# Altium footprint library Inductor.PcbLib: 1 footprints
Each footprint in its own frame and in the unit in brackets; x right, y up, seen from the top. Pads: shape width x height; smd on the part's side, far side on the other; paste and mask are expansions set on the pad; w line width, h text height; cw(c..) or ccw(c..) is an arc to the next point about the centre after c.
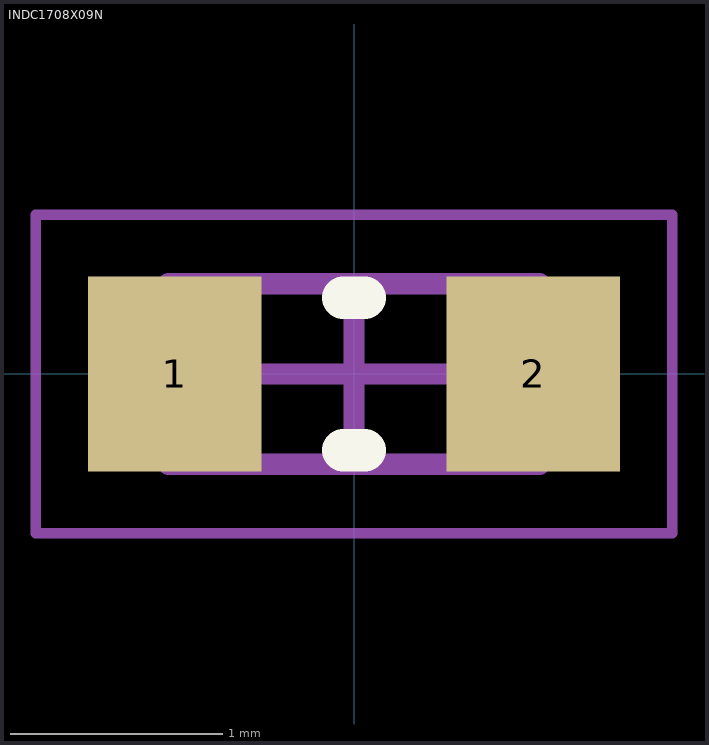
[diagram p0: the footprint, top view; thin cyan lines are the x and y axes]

## INDC1708X09N [mm] "Chip Inductor, 2-Leads, Body 1.70x0.80mm, IPC Medium Density"
height 0.9
pads (2):
  rect 0.82x0.92 smd: 1(-0.845,0) 2(0.845,0)
Top Overlay:
  lines w0.2: -0.05,-0.36 0.05,-0.36 ; -0.05,0.36 0.05,0.36
Mechanical 13:
  lines w0.1: -0.875,-0.425 0.875,-0.425 0.875,0.425 -0.875,0.425 -0.875,-0.425
Mechanical 15:
  lines w0.05: -1.5,-0.75 1.5,-0.75 1.5,0.75 -1.5,0.75 -1.5,-0.75
  lines w0.1: -0.425,0 0.425,0 ; 0,-0.425 0,0.425
3D body: height 0.9, standoff 0, extent 0.525,-0.425 0.875,0.425
3D body: height 0.9, standoff 0, extent -0.875,-0.425 -0.525,0.425
3D body: height 0.9, standoff 0, extent -0.525,-0.425 0.525,0.425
